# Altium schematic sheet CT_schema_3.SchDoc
size 299 x 185 mm
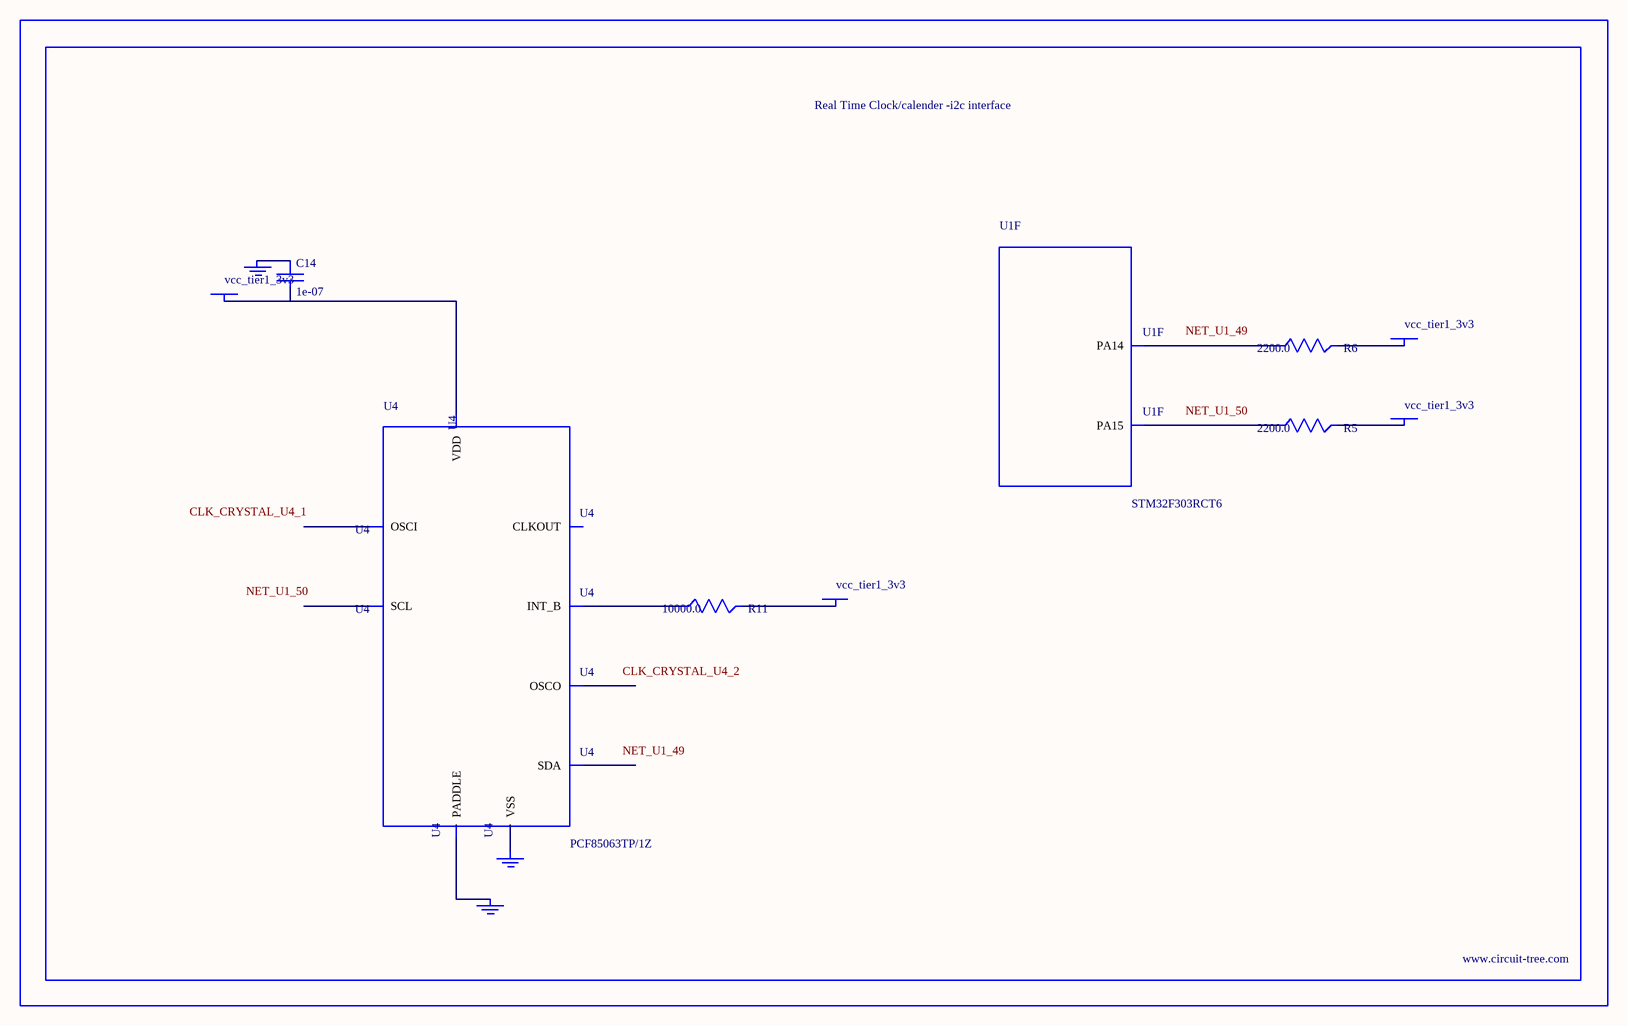
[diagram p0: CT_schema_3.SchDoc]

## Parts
BORDER2  (no value)
C14  1e-07  [C0402]
GND_INSTANCE_2_0  (no value)
GND_INSTANCE_2_1  (no value)
GND_INSTANCE_2_2  (no value)
POWER_INSTANCE_2_0  vcc_tier1_3v3
POWER_INSTANCE_2_1  vcc_tier1_3v3
POWER_INSTANCE_2_2  vcc_tier1_3v3
POWER_INSTANCE_2_3  vcc_tier1_3v3
R5  2200.0  [R0603]
R6  2200.0  [R0603]
R11  10000.0  [R0603]
U1  STM32F303RCT6  [LQFP64]  (part F of 9)
U4  PCF85063TP/1Z  [SON-8]

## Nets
NetC14_1: C14.1 GND_INSTANCE_2_0.0(GND)
NetC14_2: C14.2 POWER_INSTANCE_2_1.0(PWR) U4.8(VDD)
NetGND_INSTANCE_2_1_0: GND_INSTANCE_2_1.0(GND) U4.PAD(PADDLE)
NetGND_INSTANCE_2_2_0: GND_INSTANCE_2_2.0(GND) U4.4(VSS)
NetPOWER_INSTANCE_2_0_0: POWER_INSTANCE_2_0.0(PWR) R11.2
NetPOWER_INSTANCE_2_2_0: POWER_INSTANCE_2_2.0(PWR) R6.2
NetPOWER_INSTANCE_2_3_0: POWER_INSTANCE_2_3.0(PWR) R5.2
NetR5_1: R5.1 U1.50(PA15)
NetR6_1: R6.1 U1.49(PA14)
NetR11_1: R11.1 U4.3(INT_B)

Not connected (* = marked no-connect by the designer): U4 1(OSCI) 2(OSCO) 5(SDA) 6(SCL) 7(CLKOUT)

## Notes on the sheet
- Labels drawn without touching a wire or pin: CLK_CRYSTAL_U4_1, CLK_CRYSTAL_U4_2, NET_U1_49, NET_U1_50

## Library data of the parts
BORDER2 = BORDER_PAGE2
C14 = C0402C104K3RACTU
GND_INSTANCE_2_0-GND_INSTANCE_2_2 = GND
POWER_INSTANCE_2_0-POWER_INSTANCE_2_3 = PWR
R5 R6 = RC0603JR-072K2L
R11 = RC0603JR-0710KL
